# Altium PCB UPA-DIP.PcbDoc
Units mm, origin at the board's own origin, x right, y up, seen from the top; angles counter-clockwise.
Board outline 43.18 x 33.02 mm, 2 copper layers (Top Layer, Bottom Layer), stack 0.552 mm thick; 23 components, 25 nets, 105 pads, 4 vias.
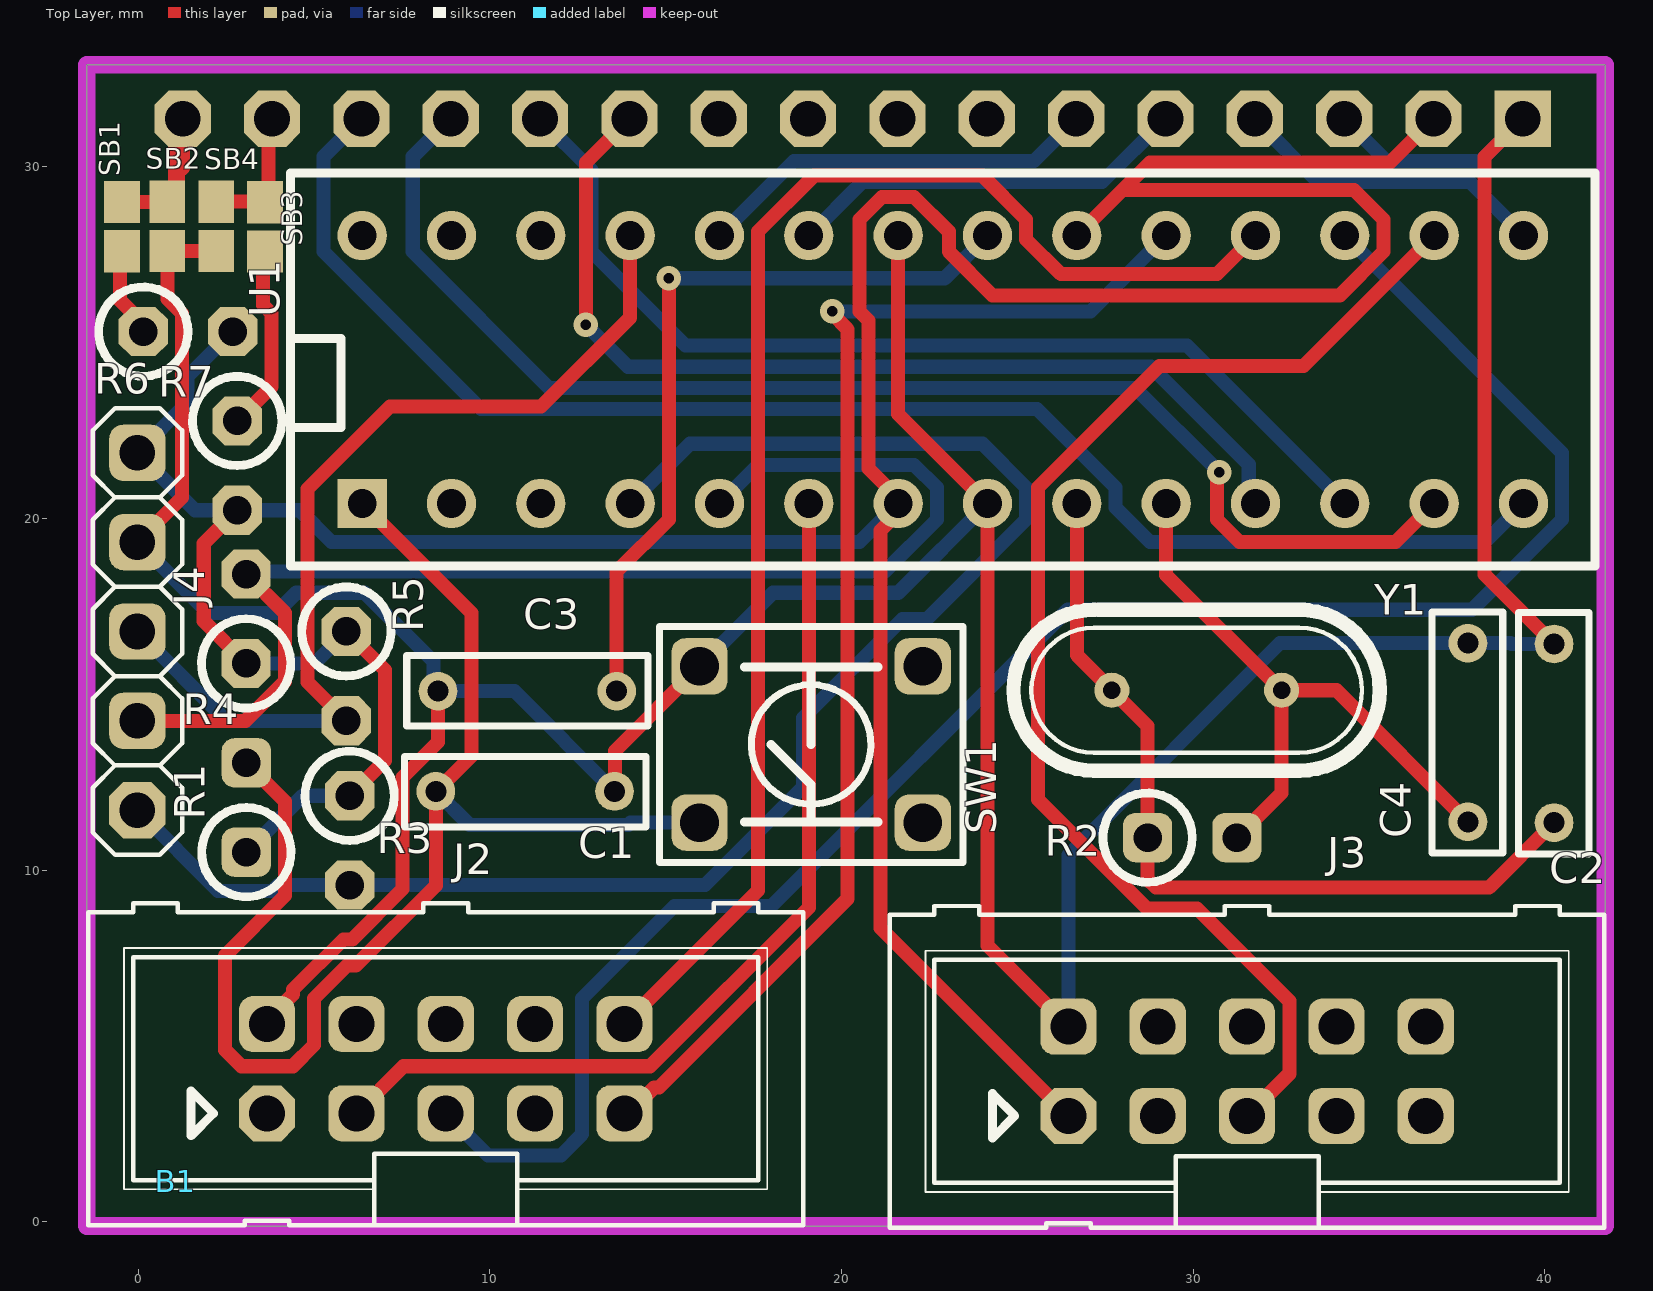
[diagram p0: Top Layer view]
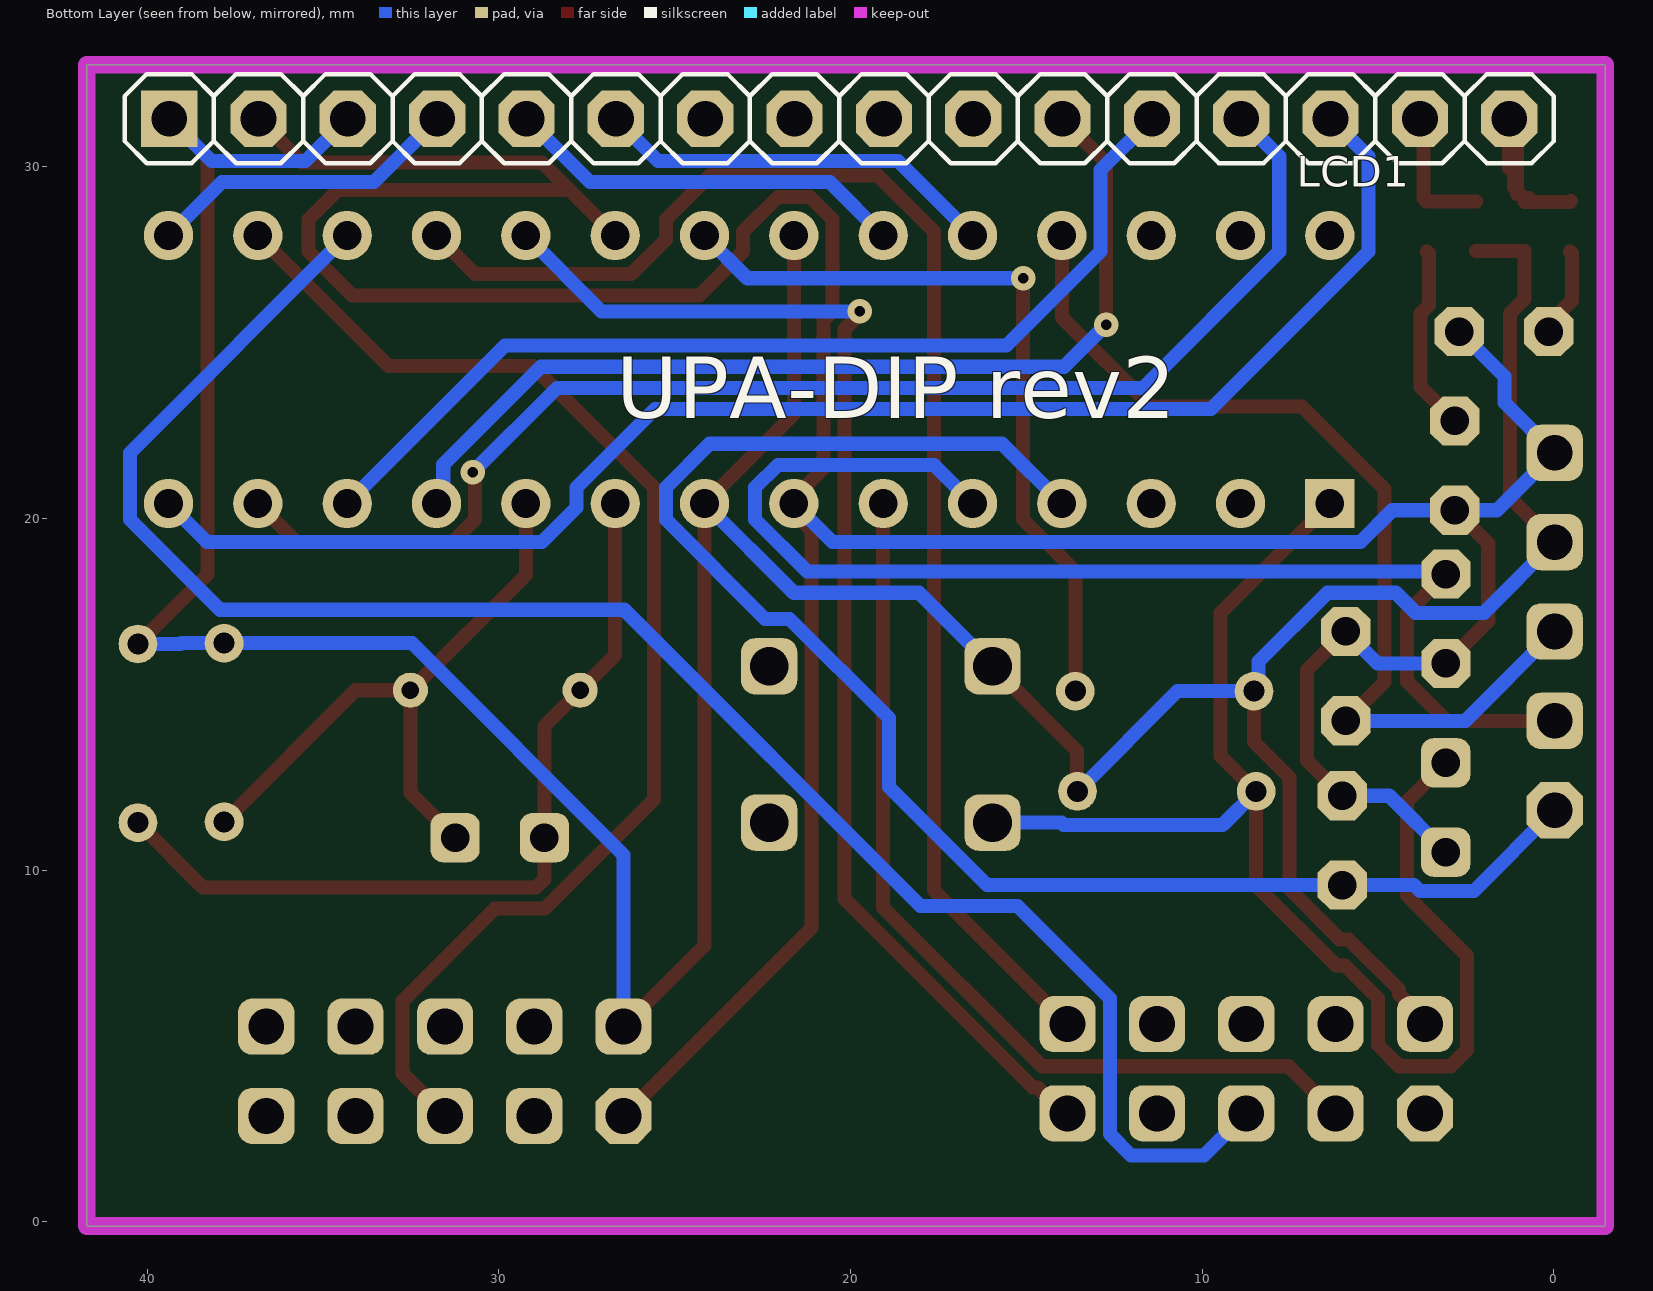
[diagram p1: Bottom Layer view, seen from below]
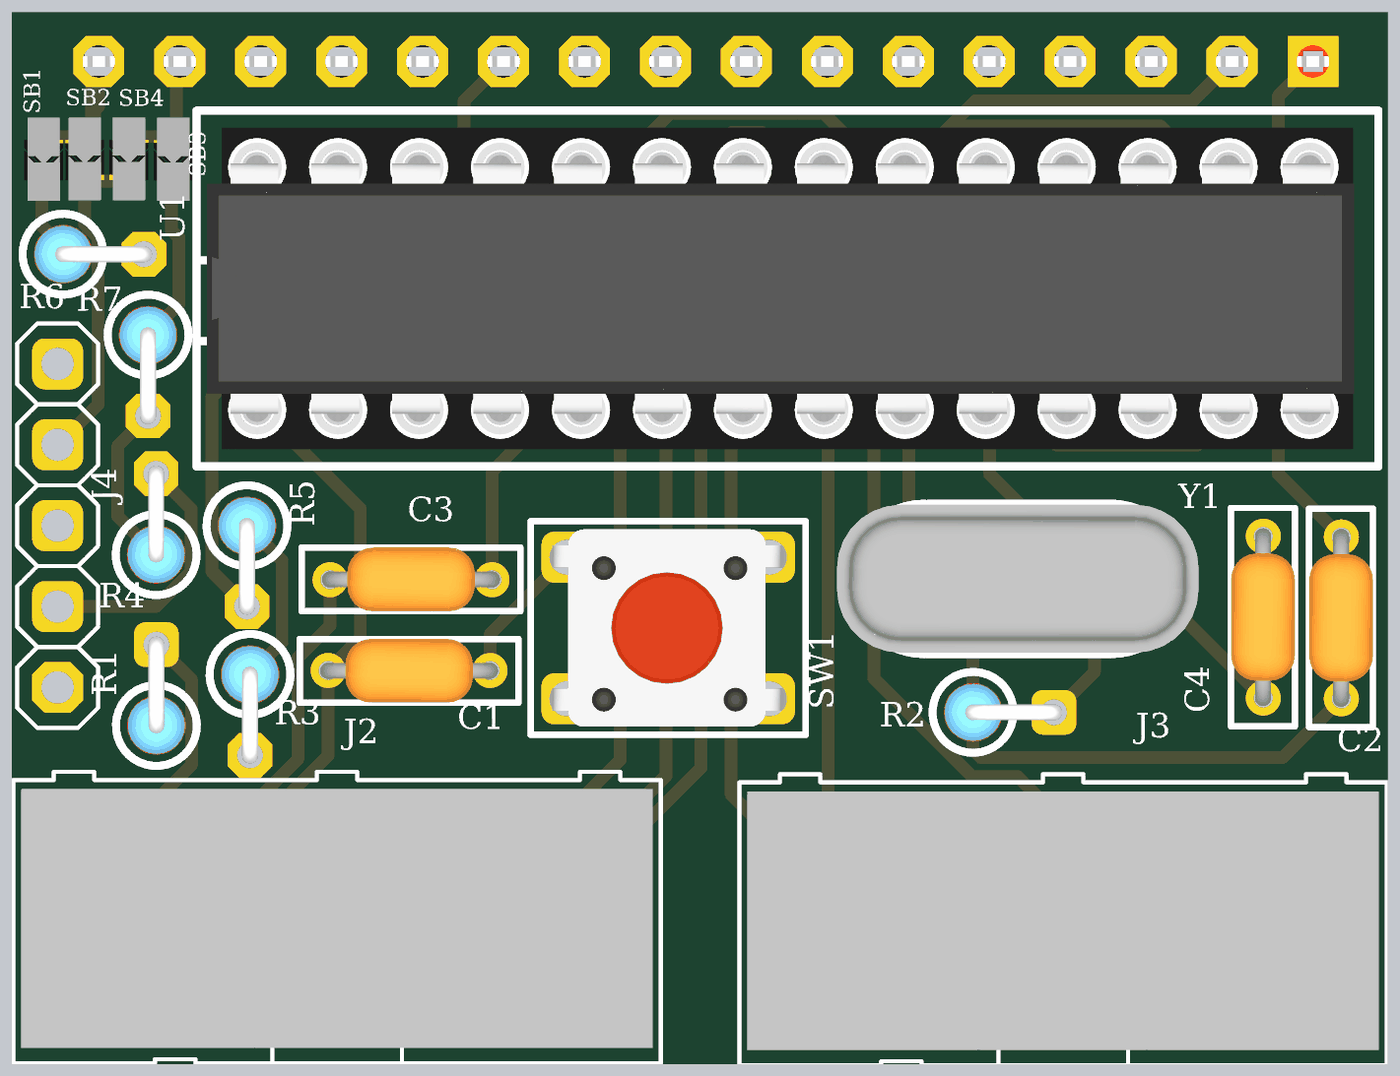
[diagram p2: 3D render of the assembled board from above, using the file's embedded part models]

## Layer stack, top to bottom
Top Solder: solder mask 0.01, Solder Resist, Dk 3.5
Top Layer: signal copper 0.036
Dielectric1: core 0.48, FR-4, Dk 4.8
Bottom Layer: signal copper 0.036
Bottom Solder: solder mask 0.01, Solder Resist, Dk 3.5

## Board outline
-1.463,-0.12 41.717,-0.12 41.717,32.9 -1.463,32.9

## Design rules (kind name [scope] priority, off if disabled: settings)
Clearance "Clearance IN CLASS 1mm" [(InNetClass('CL-1mm'))] p1 off: gap=1 ignorepadtopadclearanceinfootprint=FALSE except(0: Arc-Hole Track-Hole SMDPad-Hole THPad-Hole Via-Hole Fill-Hole Poly-Hole Region-Hole Text-Hole)
Clearance Clearance_GND_PLANE [InNamedPolygon('GND_POLY_TOP')] p2 off: gap=0.4 ignorepadtopadclearanceinfootprint=FALSE except(0: Arc-Hole Track-Hole SMDPad-Hole THPad-Hole Via-Hole Fill-Hole Poly-Hole Region-Hole Text-Hole)
Clearance Clearance_+5V_POLY [InNamedPolygon('poly_+5V-bottom')] p3 off: gap=0.5 ignorepadtopadclearanceinfootprint=FALSE except(0: Arc-Hole Track-Hole SMDPad-Hole THPad-Hole Via-Hole Fill-Hole Poly-Hole Region-Hole Text-Hole)
Clearance [All] p4: gap=0.2 ignorepadtopadclearanceinfootprint=FALSE
ComponentClearance [InComponentClass('N-DAP')] p1: gap=0.2 collisioncheckmode=3 verticalgap=0.2 showdistances=TRUE
MinimumAnnularRing [All] p1: minimumring=0.124
PlaneClearance [All] p1: clearance=0.3
PlaneConnect Plane_ConnectStyle_1 [(Name = 'C1-1') Or (Name = 'C1-2') Or (Name = 'C2-1') Or (Name = 'C2-2') Or (Name = 'C3-1') Or (Name = 'C3-2') Or (Name = 'C4-1') Or (Name = 'C4-2') Or (Name = 'C5-1') Or (Name = 'C5-2') Or (Name = 'C6-1') Or (Name = 'C6-2') Or (Name = 'C7-1')] p1 off: planeconnectstyle=Relief reliefexpansion=1.27 reliefentries=4 reliefconductorwidth=0.381 reliefairgap=0.508
PlaneConnect [All] p2: planeconnectstyle=Direct reliefexpansion=0.635 reliefentries=4 reliefconductorwidth=0.305 reliefairgap=0.254
PolygonConnect [All] p1: connectstyle=Direct reliefconductorwidth=0.254 reliefentries=4 polygonreliefangle="90 Angle" airgapwidth=0.254
RoomDefinition UPA-DIP [InComponentClass('UPA-DIP')] p1: confinementstyle=ConfineIn formatcopy=TRUE lockcomponents=FALSE outline 6.05,48.721 44.785,48.721 44.785,5.541 6.05,5.541
RoutingVias VIASWITDTH2MM [(InNetClass('W-2mm'))] p1 off: holewidth=1 width=1.8 viastyle="Through Hole" minholewidth=0.4 minwidth=0.7 maxholewidth=1 maxwidth=1.8
RoutingVias VIASWITDTH1MM [(InNetClass('W-2mm'))] p2 off: holewidth=0.5 width=1 viastyle="Through Hole" minholewidth=0.5 minwidth=1 maxholewidth=0.5 maxwidth=1
RoutingVias VIASWITDTH1.5MM [(InNetClass('W-2mm'))] p3 off: holewidth=0.9 width=1.4 viastyle="Through Hole" minholewidth=0.9 minwidth=1.4 maxholewidth=0.9 maxwidth=1.4
RoutingVias [All] p4: holewidth=0.3 width=0.7 viastyle="Through Hole" minholewidth=0.2 minwidth=0.5 maxholewidth=4 maxwidth=2
SilkToSolderMaskClearance SilkscreenOverComponentPads [IsPad] p1: minsilkscreentomaskgap=0.254 clearancetoexposedcopper=TRUE
SolderMaskExpansion [All] p1: expansion=0 istentingtop=FALSE
Width POWER-LINES [InNetClass('SUPPLY-LINES')] p1: maxlimit=2 minlimit=0.2 preferedwidth=0.4
Width [All] p2: maxlimit=2 minlimit=0.4 preferedwidth=0.4
26 further rules are at their usual default settings.

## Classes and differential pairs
component class UPA-DIP: B1 C1 C2 C3 C4 J2 J3 J4 LCD1 R1 R2 R3 R4 R5 R6 R7 SW1 U1 Y1

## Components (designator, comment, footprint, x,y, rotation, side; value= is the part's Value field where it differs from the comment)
B1 "N-GMS-NO-PINS" N-GMS-NO-PINS 1.077,1.15 r0 top locked
C1 "100nF" CK05 8.467,12.237 r0 top
C2 "18p" CK05 40.259,16.429 r270 top
C3 "100nF" CK05 13.607,15.087 r180 top
C4 "18p" CK05 37.81,16.451 r270 top
J2 "Header 5X2" ML10 8.747,4.352 r0 top
J3 "Header 5X2" ML10 31.531,4.28 r0 top
J4 "HEADER_5" 1X05 -0.021,16.784 r90 top
LCD1 "LCD MODULE SIL" 1X16-FEMALE 39.37,31.362 r180 bottom
R1 "10K" RS-2,5#1 3.078,11.779 r90 top
R2 "1M" RS-2,5#1 29.972,10.922 r0 top
R3 "10K" RS-2,5#2 6.016,10.844 r270 top
R4 "10K" RS-2,5#2 3.071,17.145 r90 top
R5 "10K" RS-2,5#2 5.92,15.514 r270 top
R6 "1Κ" RS-2,5#2 1.418,25.31 r0 top
R7 "1Κ" RS-2,5#2 2.817,21.5 r270 top
SB1 "Closed" 0603_JUMPER -0.46,28.292 r90 top
SB2 "Open" 0603_JUMPER 0.83,28.303 r90 top
SB3 "Open" 0603_JUMPER 3.607,28.29 r90 top
SB4 "Closed" 0603_JUMPER 2.219,28.303 r90 top
SW1 "EVQ-P2202M" BUTTON_6X6mm 19.137,13.571 r90 top
U1 "ATmega328PU" DIL28-300WSOCKET 6.37,20.422 r0 top
Y1 "16MHz" HC49U-V 30.107,15.104 r0 top

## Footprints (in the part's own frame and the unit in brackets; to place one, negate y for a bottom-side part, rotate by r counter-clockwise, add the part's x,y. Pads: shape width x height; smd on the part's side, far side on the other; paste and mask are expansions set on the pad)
1X05 [mil]
  oct 63x63 hole 40: 1(-200,0)
  rrect50% 63x63 hole 40: 2(-100,0) 3(0,0) 4(100,0) 5(200,0)
  silkscreen extent -250,-50 250,50
1X16-FEMALE [mil]
  rect 63x63 hole 40: 1(0,0)
  oct 63x63 hole 40: 2(100,0) 3(200,0) 4(300,0) 5(400,0) 6(500,0) 7(600,0) 8(700,0) 9(800,0) 10(900,0) 11(1000,0) 12(1100,0) 13(1200,0) 14(1300,0) 15(1400,0) 16(1500,0)
  silkscreen extent -50,-50 1550,50, body extent -55,-49 1555,49, height 335
0603_JUMPER [mm] "Jumper"
  rect 1.2x1.016 smd: 1(0.7,0) 2(-0.7,-0.003)
BUTTON_6X6mm [mm] "TACTILE BUTTON 6x6mm"
  rrect50% 1.6x1.6 hole 1.1: 1(-2.222,3.175) 2(2.223,3.175) 3(-2.222,-3.175) 4(2.223,-3.175)
  silkscreen extent -3.35,-4.32 3.35,4.32, body extent -3.1,-3.91 3.1,3.99, height 7
CK05 [mm]
  round 1.1 hole 0.6: 1(0,0) 2(5.08,0)
  silkscreen extent -0.89,-1.02 5.97,0.99, body extent -0.25,-1.01 5.33,0.99, height 6
DIL28-300WSOCKET [mm]
  rect 1.4x1.4 hole 0.813: 1(0,0)
  round 1.4 hole 0.813: 2(2.54,0) 3(5.08,0) 4(7.62,0) 5(10.16,0) 6(12.7,0) 7(15.24,0) 8(17.78,0) 9(20.32,0) 10(22.86,0) 11(25.4,0) 12(27.94,0) 13(30.48,0) 14(33.02,0) 15(33.02,7.62) 16(30.48,7.62) 17(27.94,7.62) 18(25.4,7.62) 19(22.86,7.62) 20(20.32,7.62) 21(17.78,7.62) 22(15.24,7.62) 23(12.7,7.62) 24(10.16,7.62) 25(7.62,7.62) 26(5.08,7.62) 27(2.54,7.62) 28(0,7.62)
  silkscreen extent -2.03,-1.78 35.05,9.4, body extent -1.71,-1.24 34.29,8.86, height 9.08
HC49U-V [mm]
  round 1 hole 0.5: 1(-2.421,0.009) 2(2.405,0.009)
  silkscreen extent -5.21,-2.28 5.2,2.3, body extent -5.68,-2.31 5.68,2.34, height 3.8
ML10 [mil]
  oct 63x63 hole 40.16: 1(-200,-50)
  rrect50% 63x63 hole 40.16: 2(-200,50) 3(-100,-50) 4(-100,50) 5(0,-50) 6(0,50) 7(100,-50) 8(100,50) 9(200,-50) 10(200,50)
  silkscreen extent -400,-175 400,185, body extent -400,-175 400,185, height 371
N-GMS-NO-PINS [mm]
RS-2,5#1 [mm]
  rrect50% 1.4x1.4 hole 0.813: 1(-1.27,0) 2(1.27,0)
  silkscreen extent -2.54,-1.27 0,1.27, body extent -2.19,-0.92 1.52,0.92, height 6.75
RS-2,5#2 [mm]
  oct 1.4x1.4 hole 0.813: 1(-1.27,0) 2(1.27,0)
  silkscreen extent -2.54,-1.27 0,1.27, body extent -2.19,-0.92 1.52,0.92, height 6.75

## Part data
C1 C3: library part C, "CAPACITOR", Supplier Part Number 1=594-K104K15X7RF53H5
C2 C4: library part C, "CAPACITOR"
J2 J3: "Header, 5-Pin, Dual row", Supplier Part Number 1=517-30310-6002
LCD1: library part "LCD MODULE SIL_1", "LCD MODULE SINGLE IN LINE"
R1 R3 R4 R5 R6 R7: library part R, "RESISTOR", Supplier Part Number 1=594-SFR25H0001002JR5
R2: library part R, "RESISTOR"
SB1 SB2 SB3 SB4: library part HEADER2_CIRCUIT_BRAKER, "Circuit Breaker"
SW1: library part BUTTON_TACT, "BUTTON TACTILE", Supplier Part Number 1=667-EVQ-P2202M
U1: library part ATmega48/88/168, "8-Bit AVR Microcontroller with 32K Bytes of In-System Programmable Flash Memory"
Y1: library part XTAL, "CRYSTAL"

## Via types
v1: diameter 0.7, hole 0.3, Top Layer to Bottom Layer, 4 vias

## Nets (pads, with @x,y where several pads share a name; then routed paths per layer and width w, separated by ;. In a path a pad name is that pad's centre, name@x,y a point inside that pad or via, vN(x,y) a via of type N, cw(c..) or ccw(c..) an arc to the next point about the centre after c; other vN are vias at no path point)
+5V: J3.1 J4.5 LCD1.2 R1.1 R3.1 R4.1 R5.1 R6.2 R7.2 U1.7 U1.20 | length 111.1
  Top Layer w0.4: R7.2 1.868,19.281 1.868,17.078 R4.1 ; R5.1 7.02,15.684 7.02,13.118 R3.1 ; J3.1 21.112,8.349 21.112,19.653 21.61,20.151 21.61,20.58 20.77,21.42 20.77,25.624 20.51,25.884 20.51,28.498 21.154,29.142 22.066,29.142 23.05,28.158 23.05,27.586 24.294,26.342 34.166,26.342 35.41,27.586 35.41,28.498 34.567,29.34 27.988,29.34 ; U1.20 27.988,29.34 ; LCD1.2 35.59,30.122 28.77,30.122 27.988,29.34
  Bottom Layer w0.4: R6.2 1.407,24.029 1.407,23.292 J4.5 1.613,20.23 4.596,20.23 5.504,19.322 20.51,19.322 U1.7 ; R4.1 5.011,15.875 R5.1 ; R1.1 4.683,12.114 R3.1
A2: J4.3 R5.2 U1.25 | length 27.6
  Top Layer w0.4: R5.2 4.82,15.344 4.82,20.838 7.158,23.175 11.461,23.175 13.99,25.704 U1.25
  Bottom Layer w0.4: J4.3 2.519,14.244 R5.2
D2: J4.1 R3.2 U1.4 | length 45.1
  Bottom Layer w0.4: J4.1 2.274,9.409 3.813,9.409 3.977,9.574 16.118,9.574 18.907,12.362 18.907,14.32 21.73,17.143 22.427,17.143 25.25,19.966 25.25,20.878 24.006,22.122 15.69,22.122 U1.4
D3: J4.2 R4.2 U1.5 | length 36.3
  Top Layer w0.4: J4.2 3.056,14.244 4.171,15.359 4.171,17.315 R4.2
  Bottom Layer w0.4: R4.2 3.141,18.485 21.229,18.485 22.71,19.966 22.71,20.878 22.066,21.522 17.63,21.522 U1.5
D4: J2.3 U1.6 | length 26.8
  Top Layer w0.4: J2.3 7.547,4.422 14.559,4.422 19.07,8.933 U1.6
D10: J3.5 U1.16 | length 36.4
  Top Layer w0.4: J3.5 32.731,4.21 32.731,6.281 30.107,8.905 28.688,8.905 25.59,12.003 25.59,20.878 29.043,24.33 33.138,24.33 U1.16
D11: J2.5 U1.17 | length 52.6
  Bottom Layer w0.4: J2.5 9.947,1.882 12.019,1.882 12.627,2.49 12.627,6.353 15.248,8.974 18.006,8.974 26.433,17.401 37.925,17.401 40.49,19.966 40.49,21.862 U1.17
D12: J2.10 U1.18 | length 40.9
  Top Layer w0.4: J2.10 17.63,9.425 17.63,28.158 19.214,29.742 24.006,29.742 25.25,28.498 25.25,27.926 26.234,26.942 30.67,26.942 U1.18
D13: J2.9 U1.19 | length 36.1
  Top Layer w0.4: J2.9 13.935,3.082 14.675,3.822 14.807,3.822 20.17,9.184 20.17,25.375 19.741,25.805 v1(19.741,25.886)
  Bottom Layer w0.4: v1(19.741,25.886) 27.074,25.886 U1.19
GND: C1.2 C2.1 C3.2 C4.1 J2.2 J3.2 J4.4 LCD1.1 LCD1.3 SB2.2 SB4.2 SW1.2 U1.8 U1.22 | length 122
  Top Layer w0.4: J4.4@0.006,19.352 1.248,20.593 1.248,25.826 0.833,26.241 SB2.2 0.835,27.6 2.218,27.6 SB4.2 ; J2.2 3.667,5.73 4.407,6.47 4.407,6.602 5.836,8.03 6.088,8.03 7.517,9.459 7.517,12.631 8.527,13.642 C3.2 ; C1.2 13.556,12.246 13.556,13.387 SW1.2 ; U1.22 21.61,22.962 U1.8 24.15,7.851 J3.2 ; LCD1.1 38.283,30.275 38.283,18.405 C2.1
  Bottom Layer w0.4: J4.4 1.988,17.315 3.928,17.315 4.497,17.884 6.436,17.884 8.393,15.927 8.393,15.221 C3.2 10.697,15.087 C1.2 ; SW1.2 18.053,17.885 21.613,17.885 U1.8 ; J3.2 26.451,10.432 32.471,16.451 39.023,16.451 39.046,16.429 C2.1 ; LCD1.3 35.49,30.162 38.17,30.162 LCD1.1
LCD-D4: LCD1.11 U1.11 | length 28.1
  Top Layer w0.4: v1(12.73,25.505) 12.73,30.122 LCD1.11
  Bottom Layer w0.4: v1(12.73,25.505) 13.924,24.311 28.802,24.311 31.579,21.535 31.579,20.613 U1.11
LCD-D5: LCD1.12 U1.12 | length 28.8
  Bottom Layer w0.4: LCD1.12 12.89,29.902 12.89,27.586 15.565,24.911 29.821,24.911 U1.12
LCD-D6: LCD1.13 U1.13 | length 38
  Top Layer w0.4: v1(30.739,21.314) 30.739,21.233 30.67,21.164 30.67,19.966 31.314,19.322 35.75,19.322 U1.13
  Bottom Layer w0.4: LCD1.13 7.81,30.282 7.81,27.586 11.685,23.711 28.342,23.711 v1(30.739,21.314)
LCD-D7: LCD1.14 U1.14 | length 42.6
  Bottom Layer w0.4: LCD1.14 5.27,30.282 5.27,27.586 9.745,23.111 25.556,23.111 27.79,20.878 27.79,20.306 28.774,19.322 38.29,19.322 U1.14
LCD-EN: LCD1.6 U1.24 | length 11.5
  Bottom Layer w0.4: U1.24 18.65,30.162 25.47,30.162 LCD1.6
LCD-RS: LCD1.4 U1.15 | length 9
  Bottom Layer w0.4: LCD1.4 33.55,29.562 37.87,29.562 U1.15
LCD-RW: LCD1.5 U1.23 | length 11.5
  Bottom Layer w0.4: U1.23 20.59,29.562 27.41,29.562 LCD1.5
NetC2_2: C2.2 R2.1 U1.9 Y1.1 | length 23.9
  Top Layer w0.4: U1.9 26.69,16.109 28.702,14.097 28.702,9.739 28.936,9.505 38.415,9.505 C2.2
NetC3_1: C3.1 U1.21 | length 21.9
  Top Layer w0.4: C3.1 13.607,18.484 15.092,19.969 v1(15.092,26.826)
  Bottom Layer w0.4: v1(15.092,26.826) 22.934,26.826 U1.21
NetC4_2: C4.2 R2.2 U1.10 Y1.2 | length 18.2
  Top Layer w0.4: U1.10 29.23,18.395 Y1.2 ; R2.2 32.512,12.192 Y1.2 ; C4.2 34.068,15.113 Y1.2
NetLCD1_15: LCD1.15 SB3.1 SB4.1 | length 4.1
  Top Layer w0.4: SB4.1 3.62,29.003 3.709,29.092 LCD1.15@3.709,31.079 ; LCD1.15@3.709,31.362 3.81,31.261 3.81,31.079 LCD1.15
NetLCD1_16: LCD1.16 SB1.1 SB2.1 | length 6.2
  Top Layer w0.4: SB1.1@-0.482,29.017 -0.464,28.999 0.826,28.999 SB2.1 ; SB2.1@0.712,29.113 0.848,29.113 1.138,29.403 1.138,29.83 1.27,29.962 LCD1.16 ; SB2.1@1.05,29.223 1.05,31.284 LCD1.16@1.248,31.482
NetR6_1: R6.1 SB1.2 | length 2.6
  Top Layer w0.4: SB1.2 -0.511,27.538 -0.511,26.202 0.148,25.543 R6.1
NetR7_1: R7.1 SB3.2 | length 5.3
  Top Layer w0.4: R7.1 3.788,23.741 3.788,25.826 3.551,26.063 3.551,27.532 SB3.2
RESET: C1.1 R1.2 SW1.1 U1.1 | length 38.9
  Top Layer w0.4: R1.2 4.178,11.949 4.178,9.275 2.467,7.564 2.467,4.89 2.936,4.422 4.399,4.422 5.007,5.03 5.007,6.353 5.936,7.282 6.189,7.282 8.467,9.56 C1.1 9.477,13.248 9.477,17.315 U1.1
  Bottom Layer w0.4: C1.1 9.417,11.287 13.94,11.287 14.002,11.349 SW1.1
pads on no net: J2.1 J2.4 J2.6 J2.7 J2.8 J3.3 J3.4 J3.6 J3.7 J3.8 J3.9 J3.10 LCD1.7 LCD1.8 LCD1.9 LCD1.10 SW1.3 SW1.4 U1.2 U1.3 U1.26 U1.27 U1.28

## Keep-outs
Keep-Out Layer:
  the board outline again, w0.5

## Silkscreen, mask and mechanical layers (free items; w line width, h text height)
Bottom Overlay:
  text "UPA-DIP rev2" at 26.653,22.265 h3
Mechanical 2:
  lines w0.2: 213.504,98.427 213.549,98.472
Mechanical 3:
  the board outline again, w0.25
